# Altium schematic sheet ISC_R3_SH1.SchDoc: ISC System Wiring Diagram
size B; DrawnBy: Filiberto Clara; Engineer: Filiberto Clara; Organization: LIGO Laboratory; Address1: California Institute of Technology; Address2: Massachusetts Institute of Technology; SheetNumber: 17; SheetTotal: 37
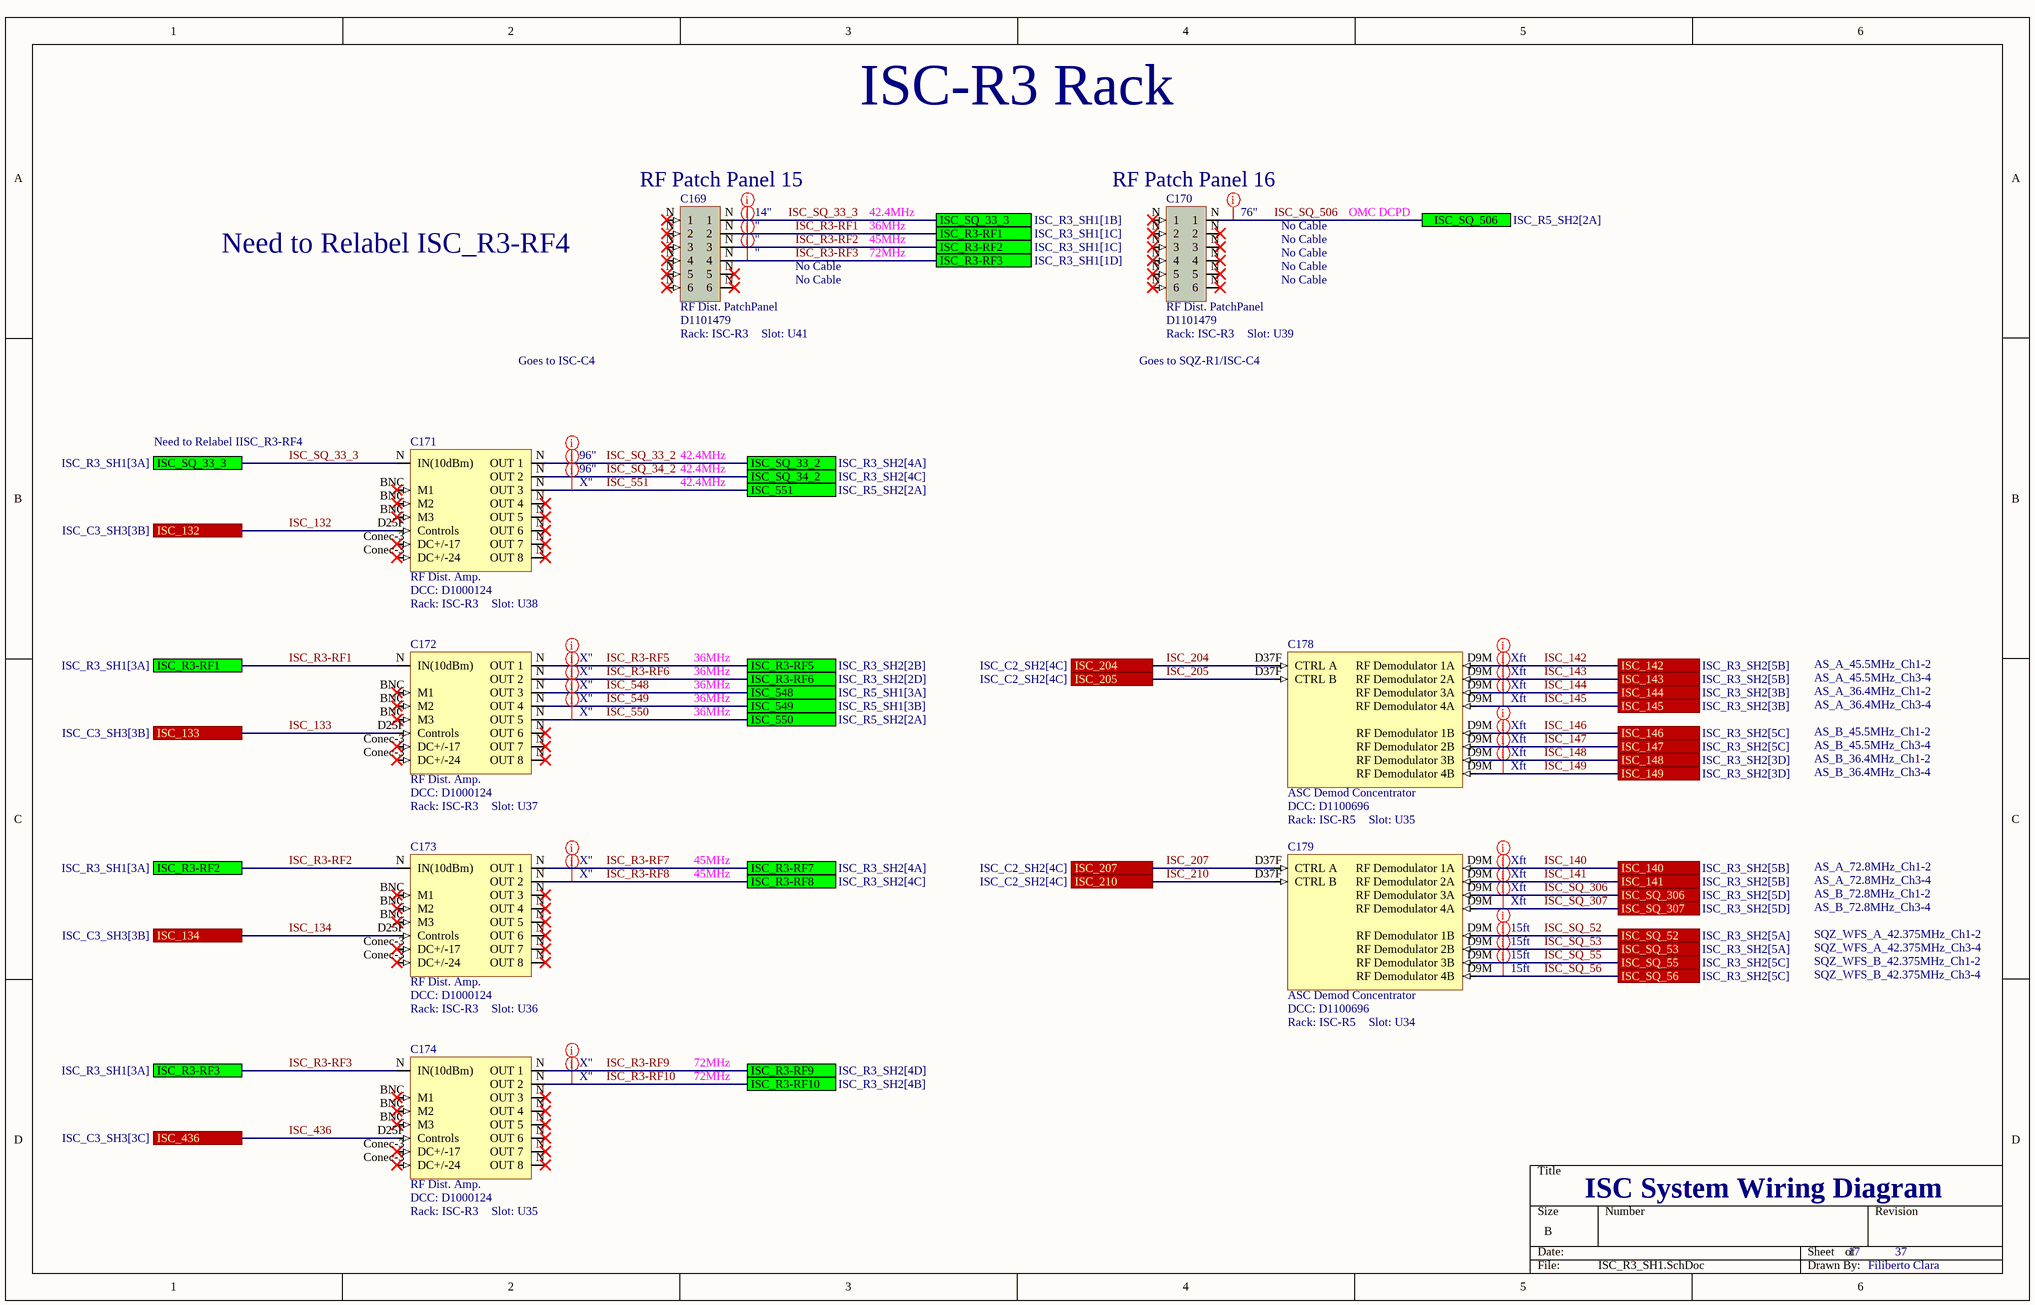
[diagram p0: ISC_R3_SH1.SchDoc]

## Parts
C169  RF Dist. PatchPanel  DCC: D1101479  Rack: ISC-R3  Slot: U41
C170  RF Dist. PatchPanel  DCC: D1101479  Rack: ISC-R3  Slot: U39
C171  RF Dist. Amp.  DCC: D1000124  Rack: ISC-R3  Slot: U38
C172  RF Dist. Amp.  DCC: D1000124  Rack: ISC-R3  Slot: U37
C173  RF Dist. Amp.  DCC: D1000124  Rack: ISC-R3  Slot: U36
C174  RF Dist. Amp.  DCC: D1000124  Rack: ISC-R3  Slot: U35
C178  ASC Demod Concentrator  DCC: D1100696  Rack: ISC-R5  Slot: U35
C179  ASC Demod Concentrator  DCC: D1100696  Rack: ISC-R5  Slot: U34

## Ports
ISC_132 (see ISC_C3_SH3[3B]), ISC_133 (see ISC_C3_SH3[3B]), ISC_134 (see ISC_C3_SH3[3B]), ISC_140 (see ISC_R3_SH2[5B]), ISC_141 (see ISC_R3_SH2[5B]), ISC_142 (see ISC_R3_SH2[5B]), ISC_143 (see ISC_R3_SH2[5B]), ISC_144 (see ISC_R3_SH2[3B]), ISC_145 (see ISC_R3_SH2[3B]), ISC_146 (see ISC_R3_SH2[5C]), ISC_147 (see ISC_R3_SH2[5C]), ISC_148 (see ISC_R3_SH2[3D]), ISC_149 (see ISC_R3_SH2[3D]), ISC_204 (see ISC_C2_SH2[4C]), ISC_205 (see ISC_C2_SH2[4C]), ISC_207 (see ISC_C2_SH2[4C]), ISC_210 (see ISC_C2_SH2[4C]), ISC_436 (see ISC_C3_SH3[3C]), ISC_548 (see ISC_R5_SH1[3A]), ISC_549 (see ISC_R5_SH1[3B]), ISC_550 (see ISC_R5_SH2[2A]), ISC_551 (see ISC_R5_SH2[2A]), ISC_R3-RF1 (see ISC_R3_SH1[1C]), ISC_R3-RF1 (see ISC_R3_SH1[3A]), ISC_R3-RF2 (see ISC_R3_SH1[1C]), ISC_R3-RF2 (see ISC_R3_SH1[3A]), ISC_R3-RF3 (see ISC_R3_SH1[1D]), ISC_R3-RF3 (see ISC_R3_SH1[3A]), ISC_R3-RF5 (see ISC_R3_SH2[2B]), ISC_R3-RF6 (see ISC_R3_SH2[2D]), ISC_R3-RF7 (see ISC_R3_SH2[4A]), ISC_R3-RF8 (see ISC_R3_SH2[4C]), ISC_R3-RF9 (see ISC_R3_SH2[4D]), ISC_R3-RF10 (see ISC_R3_SH2[4B]), ISC_SQ_33_2 (see ISC_R3_SH2[4A]), ISC_SQ_33_3 (see ISC_R3_SH1[1B]), ISC_SQ_33_3 (see ISC_R3_SH1[3A]), ISC_SQ_34_2 (see ISC_R3_SH2[4C]), ISC_SQ_52 (see ISC_R3_SH2[5A]), ISC_SQ_53 (see ISC_R3_SH2[5A]), ISC_SQ_55 (see ISC_R3_SH2[5C]), ISC_SQ_56 (see ISC_R3_SH2[5C]), ISC_SQ_306 (see ISC_R3_SH2[5D]), ISC_SQ_307 (see ISC_R3_SH2[5D]), ISC_SQ_506 (see ISC_R5_SH2[2A])

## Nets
ISC_132: C171.D25F(Controls) ; port ISC_132
ISC_133: C172.D25F(Controls) ; port ISC_133
ISC_134: C173.D25F(Controls) ; port ISC_134
ISC_140: C179.D9M(RF_Demodulator_1A) ; port ISC_140
ISC_141: C179.D9M(RF_Demodulator_2A) ; port ISC_141
ISC_142: C178.D9M(RF_Demodulator_1A) ; port ISC_142
ISC_143: C178.D9M(RF_Demodulator_2A) ; port ISC_143
ISC_144: C178.D9M(RF_Demodulator_3A) ; port ISC_144
ISC_145: C178.D9M(RF_Demodulator_4A) ; port ISC_145
ISC_146: C178.D9M(RF_Demodulator_1B) ; port ISC_146
ISC_147: C178.D9M(RF_Demodulator_2B) ; port ISC_147
ISC_148: C178.D9M(RF_Demodulator_3B) ; port ISC_148
ISC_149: C178.D9M(RF_Demodulator_4B) ; port ISC_149
ISC_204: C178.D37F(CTRL_A) ; port ISC_204
ISC_205: C178.D37F(CTRL_B) ; port ISC_205
ISC_207: C179.D37F(CTRL_A) ; port ISC_207
ISC_210: C179.D37F(CTRL_B) ; port ISC_210
ISC_436: C174.D25F(Controls) ; port ISC_436
ISC_548: C172.N(OUT_3) ; port ISC_548
ISC_549: C172.N(OUT_4) ; port ISC_549
ISC_550: C172.N(OUT_5) ; port ISC_550
ISC_551: C171.N(OUT_3) ; port ISC_551
ISC_R3-RF1: C169.N(2) C172.N(IN(10dBm)) ; port ISC_R3-RF1
ISC_R3-RF2: C169.N(3) C173.N(IN(10dBm)) ; port ISC_R3-RF2
ISC_R3-RF3: C169.N(4) C174.N(IN(10dBm)) ; port ISC_R3-RF3
ISC_R3-RF5: C172.N(OUT_1) ; port ISC_R3-RF5
ISC_R3-RF6: C172.N(OUT_2) ; port ISC_R3-RF6
ISC_R3-RF7: C173.N(OUT_1) ; port ISC_R3-RF7
ISC_R3-RF8: C173.N(OUT_2) ; port ISC_R3-RF8
ISC_R3-RF9: C174.N(OUT_1) ; port ISC_R3-RF9
ISC_R3-RF10: C174.N(OUT_2) ; port ISC_R3-RF10
ISC_SQ_33_2: C171.N(OUT_1) ; port ISC_SQ_33_2
ISC_SQ_33_3: C169.N(1) C171.N(IN(10dBm)) ; port ISC_SQ_33_3
ISC_SQ_34_2: C171.N(OUT_2) ; port ISC_SQ_34_2
ISC_SQ_52: C179.D9M(RF_Demodulator_1B) ; port ISC_SQ_52
ISC_SQ_53: C179.D9M(RF_Demodulator_2B) ; port ISC_SQ_53
ISC_SQ_55: C179.D9M(RF_Demodulator_3B) ; port ISC_SQ_55
ISC_SQ_56: C179.D9M(RF_Demodulator_4B) ; port ISC_SQ_56
ISC_SQ_306: C179.D9M(RF_Demodulator_3A) ; port ISC_SQ_306
ISC_SQ_307: C179.D9M(RF_Demodulator_4A) ; port ISC_SQ_307
ISC_SQ_506: C170.N(1) ; port ISC_SQ_506

Not connected (* = marked no-connect by the designer): C171 BNC(M1)* Conec-3(DC+/-17)*; C172 BNC(M1)* Conec-3(DC+/-17)*; C173 BNC(M1)* Conec-3(DC+/-17)*; C174 BNC(M1)* Conec-3(DC+/-17)*

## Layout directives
Length: ": ISC_R3-RF1, ISC_R3-RF2, ISC_R3-RF3
Length: 96": ISC_SQ_33_2, ISC_SQ_34_2
Length: X": ISC_548, ISC_549, ISC_550, ISC_551, ISC_R3-RF5, ISC_R3-RF6, ISC_R3-RF7, ISC_R3-RF8, ISC_R3-RF9, ISC_R3-RF10
Length: 14": ISC_SQ_33_3
Length: 76": ISC_SQ_506
Length: 15ft: ISC_SQ_52, ISC_SQ_53, ISC_SQ_55, ISC_SQ_56
Length: Xft: ISC_140, ISC_141, ISC_142, ISC_143, ISC_144, ISC_145, ISC_146, ISC_147, ISC_148, ISC_149, ISC_SQ_306, ISC_SQ_307

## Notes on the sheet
- ISC-R3 Rack
- (near C169) RF Patch Panel 15
- 36MHz
- 45MHz
- 42.4MHz
- (near C170) RF Patch Panel 16
- No Cable
- OMC DCPD
- Need to Relabel ISC_R3-RF4
- 72MHz
- Goes to ISC-C4
- Goes to SQZ-R1/ISC-C4
- Need to Relabel IISC_R3-RF4
- AS_A_45.5MHz_Ch1-2
- AS_A_45.5MHz_Ch3-4
- AS_A_36.4MHz_Ch1-2
- AS_A_36.4MHz_Ch3-4
- AS_B_45.5MHz_Ch1-2
- AS_B_45.5MHz_Ch3-4
- AS_B_36.4MHz_Ch1-2
- AS_B_36.4MHz_Ch3-4
- AS_A_72.8MHz_Ch1-2
- AS_A_72.8MHz_Ch3-4
- AS_B_72.8MHz_Ch1-2
- AS_B_72.8MHz_Ch3-4
- SQZ_WFS_A_42.375MHz_Ch1-2
- SQZ_WFS_A_42.375MHz_Ch3-4
- SQZ_WFS_B_42.375MHz_Ch1-2
- SQZ_WFS_B_42.375MHz_Ch3-4

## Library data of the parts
C169 C170 = RF Dist. PatchPanel: Serial: Sxxxxxxx; System: ISC
C171-C174 = RF Distribution Amplifier: Serial: Sxxxxxxx; System: ISC
C178 C179 = ASC Demod Concentrator: Serial: Sxxxxxxx; System: ISC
